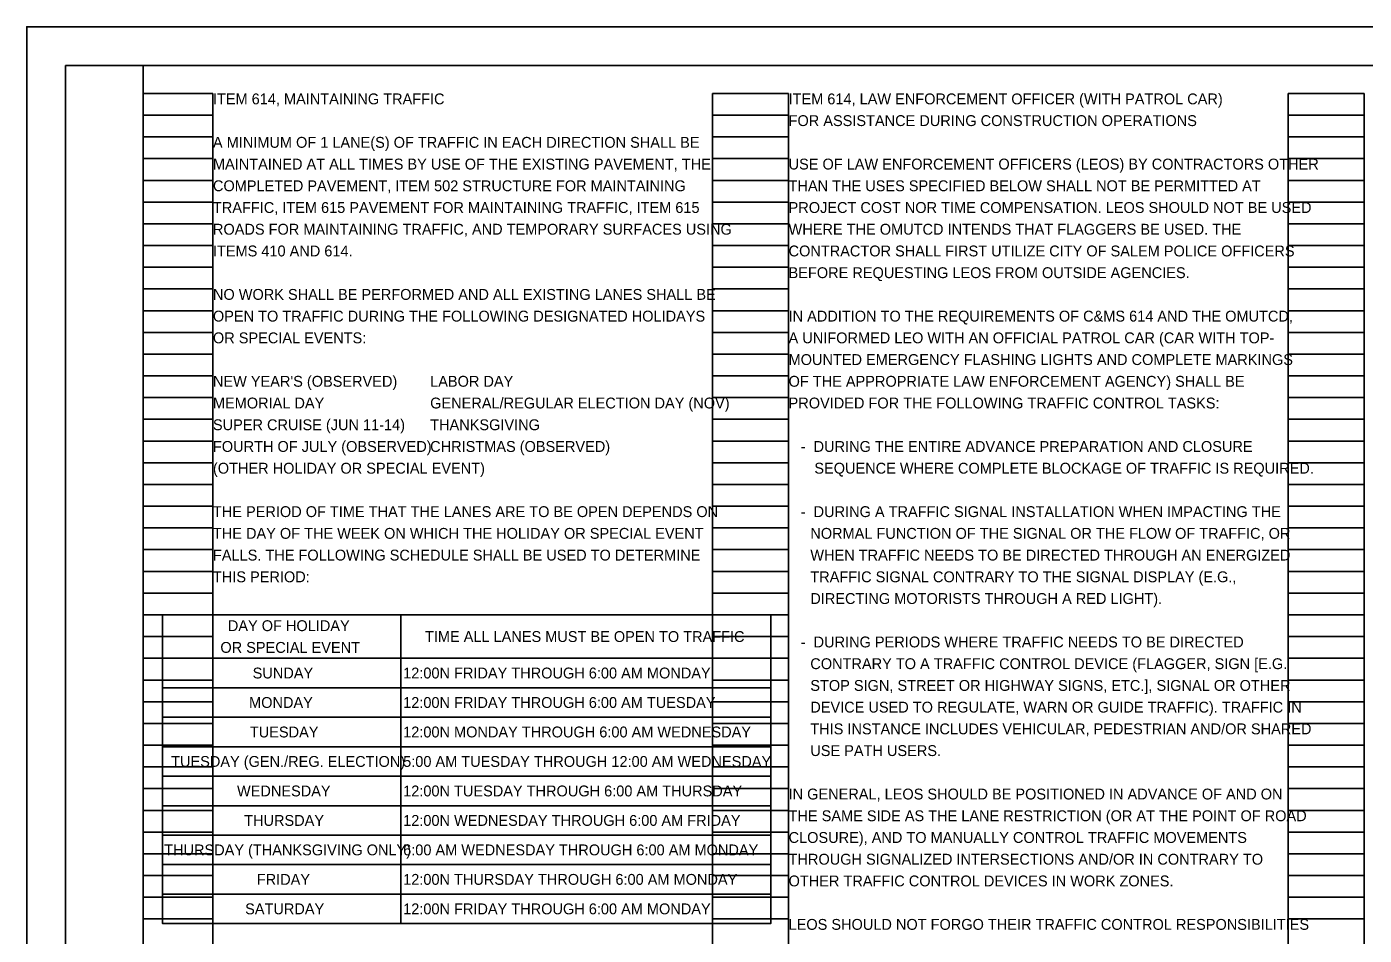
# Model space of a CAD drawing. Extents: x 0 to 34, y 0 to 22.
# Drawn here: x 0 to 17.24, y 10.29 to 22 of the extents above; entities that cross this region are included whole.
import ezdxf

# ---------------------------------------------------------------- set-up
doc = ezdxf.new("R2010")
doc.units = 0
for name, color, linetype in [('SH_Border', 7, 'Continuous'), ('SH_Cut_Line', 7, 'Continuous'), ('SH_Data', 7, 'Continuous'), ('SH_Text', 7, 'Continuous')]:
    doc.layers.add(name, color=color, linetype=linetype)

msp = doc.modelspace()

# ---------------------------------------------------------------- linework, layer by layer
at = {"layer": 'SH_Border'}
for points in [[(0.5, 21.5), (1.5, 21.5), (1.5, 0.5), (0.5, 0.5)], [(1.5, 21.5), (33.5, 21.5), (33.5, 0.5), (1.5, 0.5)]]:
    msp.add_lwpolyline(points, close=True, dxfattribs=at)
at = {"layer": 'SH_Cut_Line'}
msp.add_lwpolyline([(0, 0), (34, 0), (34, 22), (0, 22)], close=True, dxfattribs=at)
at = {"layer": 'SH_Data'}
for p, q in [((1.5, 0.98), (1.5, 21.14)), ((1.5, 21.14), (2.4, 21.14)), ((2.4, 0.98), (2.4, 21.14)), ((8.84, 0.98), (8.84, 21.14)), ((8.84, 21.14), (9.82, 21.14)), ((9.82, 0.98), (9.82, 21.14)), ((16.26, 0.98), (16.26, 21.14)), ((16.26, 21.14), (17.24, 21.14)), ((17.24, 0.98), (17.24, 21.14)), ((1.5, 20.86), (2.4, 20.86)), ((8.84, 20.86), (9.82, 20.86)), ((16.26, 20.86), (17.24, 20.86)), ((1.5, 20.58), (2.4, 20.58)), ((8.84, 20.58), (9.82, 20.58)), ((16.26, 20.58), (17.24, 20.58)), ((1.5, 20.3), (2.4, 20.3)), ((8.84, 20.3), (9.82, 20.3)), ((16.26, 20.3), (17.24, 20.3)), ((1.5, 20.02), (2.4, 20.02)), ((8.84, 20.02), (9.82, 20.02)), ((16.26, 20.02), (17.24, 20.02)), ((1.5, 19.74), (2.4, 19.74)), ((8.84, 19.74), (9.82, 19.74)), ((16.26, 19.74), (17.24, 19.74)), ((1.5, 19.46), (2.4, 19.46)), ((8.84, 19.46), (9.82, 19.46)), ((16.26, 19.46), (17.24, 19.46)), ((1.5, 19.18), (2.4, 19.18)), ((8.84, 19.18), (9.82, 19.18)), ((16.26, 19.18), (17.24, 19.18)), ((1.5, 18.9), (2.4, 18.9)), ((8.84, 18.9), (9.82, 18.9)), ((16.26, 18.9), (17.24, 18.9)), ((1.5, 18.62), (2.4, 18.62)), ((8.84, 18.62), (9.82, 18.62)), ((16.26, 18.62), (17.24, 18.62)), ((1.5, 18.34), (2.4, 18.34)), ((8.84, 18.34), (9.82, 18.34)), ((16.26, 18.34), (17.24, 18.34)), ((1.5, 18.06), (2.4, 18.06)), ((8.84, 18.06), (9.82, 18.06)), ((16.26, 18.06), (17.24, 18.06)), ((1.5, 17.78), (2.4, 17.78)), ((8.84, 17.78), (9.82, 17.78)), ((16.26, 17.78), (17.24, 17.78)), ((1.5, 17.5), (2.4, 17.5)), ((8.84, 17.5), (9.82, 17.5)), ((16.26, 17.5), (17.24, 17.5)), ((1.5, 17.22), (2.4, 17.22)), ((8.84, 17.22), (9.82, 17.22)), ((16.26, 17.22), (17.24, 17.22)), ((1.5, 16.94), (2.4, 16.94)), ((8.84, 16.94), (9.82, 16.94)), ((16.26, 16.94), (17.24, 16.94)), ((1.5, 16.66), (2.4, 16.66)), ((8.84, 16.66), (9.82, 16.66)), ((16.26, 16.66), (17.24, 16.66)), ((1.5, 16.38), (2.4, 16.38)), ((8.84, 16.38), (9.82, 16.38)), ((16.26, 16.38), (17.24, 16.38)), ((1.5, 16.1), (2.4, 16.1)), ((8.84, 16.1), (9.82, 16.1)), ((16.26, 16.1), (17.24, 16.1)), ((1.5, 15.82), (2.4, 15.82)), ((8.84, 15.82), (9.82, 15.82)), ((16.26, 15.82), (17.24, 15.82)), ((1.5, 15.54), (2.4, 15.54)), ((8.84, 15.54), (9.82, 15.54)), ((16.26, 15.54), (17.24, 15.54)), ((1.5, 15.26), (2.4, 15.26)), ((8.84, 15.26), (9.82, 15.26)), ((16.26, 15.26), (17.24, 15.26)), ((1.5, 14.98), (2.4, 14.98)), ((8.84, 14.98), (9.82, 14.98)), ((16.26, 14.98), (17.24, 14.98)), ((1.5, 14.7), (2.4, 14.7)), ((8.84, 14.7), (9.82, 14.7)), ((16.26, 14.7), (17.24, 14.7)), ((1.5, 14.42), (2.4, 14.42)), ((8.84, 14.42), (9.82, 14.42)), ((16.26, 14.42), (17.24, 14.42)), ((1.5, 14.14), (2.4, 14.14)), ((8.84, 14.14), (9.82, 14.14)), ((16.26, 14.14), (17.24, 14.14)), ((1.5, 13.86), (2.4, 13.86)), ((8.84, 13.86), (9.82, 13.86)), ((16.26, 13.86), (17.24, 13.86)), ((1.5, 13.58), (2.4, 13.58)), ((8.84, 13.58), (9.82, 13.58)), ((16.26, 13.58), (17.24, 13.58)), ((1.5, 13.3), (2.4, 13.3)), ((8.84, 13.3), (9.82, 13.3)), ((16.26, 13.3), (17.24, 13.3)), ((1.5, 13.02), (2.4, 13.02)), ((8.84, 13.02), (9.82, 13.02)), ((16.26, 13.02), (17.24, 13.02)), ((1.5, 12.74), (2.4, 12.74)), ((8.84, 12.74), (9.82, 12.74)), ((16.26, 12.74), (17.24, 12.74)), ((1.5, 12.46), (2.4, 12.46)), ((8.84, 12.46), (9.82, 12.46)), ((16.26, 12.46), (17.24, 12.46)), ((1.5, 12.18), (2.4, 12.18)), ((8.84, 12.18), (9.82, 12.18)), ((16.26, 12.18), (17.24, 12.18)), ((1.5, 11.9), (2.4, 11.9)), ((8.84, 11.9), (9.82, 11.9)), ((16.26, 11.9), (17.24, 11.9)), ((1.5, 11.62), (2.4, 11.62)), ((8.84, 11.62), (9.82, 11.62)), ((16.26, 11.62), (17.24, 11.62)), ((1.5, 11.34), (2.4, 11.34)), ((8.84, 11.34), (9.82, 11.34)), ((16.26, 11.34), (17.24, 11.34)), ((1.5, 11.06), (2.4, 11.06)), ((8.84, 11.06), (9.82, 11.06)), ((16.26, 11.06), (17.24, 11.06)), ((1.5, 10.78), (2.4, 10.78)), ((8.84, 10.78), (9.82, 10.78)), ((16.26, 10.78), (17.24, 10.78)), ((1.5, 10.5), (2.4, 10.5)), ((8.84, 10.5), (9.82, 10.5)), ((16.26, 10.5), (17.24, 10.5))]:
    msp.add_line(p, q, dxfattribs=at)
at = {"layer": 'SH_Text'}
for points in [[(1.75, 14.42), (4.82, 14.42), (4.82, 13.86), (1.75, 13.86)], [(4.82, 14.42), (9.59, 14.42), (9.59, 13.86), (4.82, 13.86)], [(1.75, 13.86), (4.82, 13.86), (4.82, 13.48), (1.75, 13.48)], [(4.82, 13.86), (9.59, 13.86), (9.59, 13.48), (4.82, 13.48)], [(1.75, 13.48), (4.82, 13.48), (4.82, 13.1), (1.75, 13.1)], [(4.82, 13.48), (9.59, 13.48), (9.59, 13.1), (4.82, 13.1)], [(1.75, 13.1), (4.82, 13.1), (4.82, 12.72), (1.75, 12.72)], [(4.82, 13.1), (9.59, 13.1), (9.59, 12.72), (4.82, 12.72)], [(1.75, 12.72), (4.82, 12.72), (4.82, 12.34), (1.75, 12.34)], [(4.82, 12.72), (9.59, 12.72), (9.59, 12.34), (4.82, 12.34)], [(1.75, 12.34), (4.82, 12.34), (4.82, 11.96), (1.75, 11.96)], [(4.82, 12.34), (9.59, 12.34), (9.59, 11.96), (4.82, 11.96)], [(1.75, 11.96), (4.82, 11.96), (4.82, 11.58), (1.75, 11.58)], [(4.82, 11.96), (9.59, 11.96), (9.59, 11.58), (4.82, 11.58)], [(1.75, 11.58), (4.82, 11.58), (4.82, 11.2), (1.75, 11.2)], [(4.82, 11.58), (9.59, 11.58), (9.59, 11.2), (4.82, 11.2)], [(1.75, 11.2), (4.82, 11.2), (4.82, 10.82), (1.75, 10.82)], [(4.82, 11.2), (9.59, 11.2), (9.59, 10.82), (4.82, 10.82)], [(1.75, 10.82), (4.82, 10.82), (4.82, 10.44), (1.75, 10.44)], [(4.82, 10.82), (9.59, 10.82), (9.59, 10.44), (4.82, 10.44)]]:
    msp.add_lwpolyline(points, close=True, dxfattribs=at)

# ---------------------------------------------------------------- texts
for s, p in [('ITEM 614, MAINTAINING TRAFFIC', (2.4, 21)), ('ITEM 614, LAW ENFORCEMENT OFFICER (WITH PATROL CAR)', (9.82, 21)), ('FOR ASSISTANCE DURING CONSTRUCTION OPERATIONS', (9.82, 20.72)), ('A MINIMUM OF 1 LANE(S) OF TRAFFIC IN EACH DIRECTION SHALL BE ', (2.4, 20.44)), ('MAINTAINED AT ALL TIMES BY USE OF THE EXISTING PAVEMENT, THE ', (2.4, 20.16)), ('USE OF LAW ENFORCEMENT OFFICERS (LEOS) BY CONTRACTORS OTHER ', (9.82, 20.16)), ('COMPLETED PAVEMENT, ITEM 502 STRUCTURE FOR MAINTAINING ', (2.4, 19.88)), ('THAN THE USES SPECIFIED BELOW SHALL NOT BE PERMITTED AT ', (9.82, 19.88)), ('TRAFFIC, ITEM 615 PAVEMENT FOR MAINTAINING TRAFFIC, ITEM 615 ', (2.4, 19.6)), ('PROJECT COST NOR TIME COMPENSATION. LEOS SHOULD NOT BE USED ', (9.82, 19.6)), ('ROADS FOR MAINTAINING TRAFFIC, AND TEMPORARY SURFACES USING ', (2.4, 19.32)), ('WHERE THE OMUTCD INTENDS THAT FLAGGERS BE USED. THE ', (9.82, 19.32)), ('ITEMS 410 AND 614.', (2.4, 19.04)), ('CONTRACTOR SHALL FIRST UTILIZE CITY OF SALEM POLICE OFFICERS ', (9.82, 19.04)), ('BEFORE REQUESTING LEOS FROM OUTSIDE AGENCIES.', (9.82, 18.76)), ('NO WORK SHALL BE PERFORMED AND ALL EXISTING LANES SHALL BE', (2.4, 18.48)), ('OPEN TO TRAFFIC DURING THE FOLLOWING DESIGNATED HOLIDAYS', (2.4, 18.2)), ('IN ADDITION TO THE REQUIREMENTS OF C&MS 614 AND THE OMUTCD, ', (9.82, 18.2)), ('OR SPECIAL EVENTS:', (2.4, 17.92)), ('A UNIFORMED LEO WITH AN OFFICIAL PATROL CAR (CAR WITH TOP-', (9.82, 17.92)), ('MOUNTED EMERGENCY FLASHING LIGHTS AND COMPLETE MARKINGS ', (9.82, 17.64)), ("NEW YEAR'S (OBSERVED)      ", (2.4, 17.36)), ('LABOR DAY', (5.2, 17.36)), ('OF THE APPROPRIATE LAW ENFORCEMENT AGENCY) SHALL BE ', (9.82, 17.36)), ('MEMORIAL DAY ', (2.4, 17.08)), ('GENERAL/REGULAR ELECTION DAY (NOV)', (5.2, 17.08)), ('PROVIDED FOR THE FOLLOWING TRAFFIC CONTROL TASKS:', (9.82, 17.08)), ('SUPER CRUISE (JUN 11-14)', (2.4, 16.8)), ('THANKSGIVING    ', (5.2, 16.8)), ('FOURTH OF JULY (OBSERVED)', (2.4, 16.52)), ('CHRISTMAS (OBSERVED)', (5.2, 16.52)), ('   -  DURING THE ENTIRE ADVANCE PREPARATION AND CLOSURE ', (9.82, 16.52)), ('(OTHER HOLIDAY OR SPECIAL EVENT)', (2.4, 16.24)), (' SEQUENCE WHERE COMPLETE BLOCKAGE OF TRAFFIC IS REQUIRED.', (10.1, 16.24)), ('THE PERIOD OF TIME THAT THE LANES ARE TO BE OPEN DEPENDS ON', (2.4, 15.68)), ('   -  DURING A TRAFFIC SIGNAL INSTALLATION WHEN IMPACTING THE ', (9.82, 15.68)), ('THE DAY OF THE WEEK ON WHICH THE HOLIDAY OR SPECIAL EVENT ', (2.4, 15.4)), ('NORMAL FUNCTION OF THE SIGNAL OR THE FLOW OF TRAFFIC, OR ', (10.1, 15.4)), ('FALLS. THE FOLLOWING SCHEDULE SHALL BE USED TO DETERMINE', (2.4, 15.12)), ('WHEN TRAFFIC NEEDS TO BE DIRECTED THROUGH AN ENERGIZED ', (10.1, 15.12)), ('THIS PERIOD:', (2.4, 14.84)), ('TRAFFIC SIGNAL CONTRARY TO THE SIGNAL DISPLAY (E.G., ', (10.1, 14.84)), ('DIRECTING MOTORISTS THROUGH A RED LIGHT).', (10.1, 14.56)), ('DAY OF HOLIDAY', (2.592, 14.21)), ('TIME ALL LANES MUST BE OPEN TO TRAFFIC', (5.133, 14.07)), ('   -  DURING PERIODS WHERE TRAFFIC NEEDS TO BE DIRECTED ', (9.82, 14)), ('OR SPECIAL EVENT', (2.496, 13.93)), ('CONTRARY TO A TRAFFIC CONTROL DEVICE (FLAGGER, SIGN [E.G. ', (10.1, 13.72)), ('SUNDAY', (2.912, 13.6)), ('12:00N FRIDAY THROUGH 6:00 AM MONDAY', (4.852, 13.6)), ('STOP SIGN, STREET OR HIGHWAY SIGNS, ETC.], SIGNAL OR OTHER ', (10.1, 13.44)), ('MONDAY', (2.866, 13.22)), ('12:00N FRIDAY THROUGH 6:00 AM TUESDAY', (4.852, 13.22)), ('DEVICE USED TO REGULATE, WARN OR GUIDE TRAFFIC). TRAFFIC IN ', (10.1, 13.16)), ('TUESDAY', (2.876, 12.84)), ('12:00N MONDAY THROUGH 6:00 AM WEDNESDAY', (4.852, 12.84)), ('THIS INSTANCE INCLUDES VEHICULAR, PEDESTRIAN AND/OR SHARED ', (10.1, 12.88)), ('TUESDAY (GEN./REG. ELECTION)', (1.861, 12.46)), ('5:00 AM TUESDAY THROUGH 12:00 AM WEDNESDAY', (4.852, 12.46)), ('USE PATH USERS.', (10.1, 12.6)), ('WEDNESDAY', (2.71, 12.08)), ('12:00N TUESDAY THROUGH 6:00 AM THURSDAY', (4.852, 12.08)), ('IN GENERAL, LEOS SHOULD BE POSITIONED IN ADVANCE OF AND ON ', (9.82, 12.04)), ('THE SAME SIDE AS THE LANE RESTRICTION (OR AT THE POINT OF ROAD ', (9.82, 11.76)), ('THURSDAY', (2.802, 11.7)), ('12:00N WEDNESDAY THROUGH 6:00 AM FRIDAY', (4.852, 11.7)), ('CLOSURE), AND TO MANUALLY CONTROL TRAFFIC MOVEMENTS ', (9.82, 11.48)), ('THURSDAY (THANKSGIVING ONLY)', (1.771, 11.32)), ('6:00 AM WEDNESDAY THROUGH 6:00 AM MONDAY', (4.852, 11.32)), ('THROUGH SIGNALIZED INTERSECTIONS AND/OR IN CONTRARY TO ', (9.82, 11.2)), ('FRIDAY', (2.965, 10.94)), ('12:00N THURSDAY THROUGH 6:00 AM MONDAY', (4.852, 10.94)), ('OTHER TRAFFIC CONTROL DEVICES IN WORK ZONES.', (9.82, 10.92)), ('SATURDAY', (2.815, 10.56)), ('12:00N FRIDAY THROUGH 6:00 AM MONDAY', (4.852, 10.56)), ('LEOS SHOULD NOT FORGO THEIR TRAFFIC CONTROL RESPONSIBILITIES ', (9.82, 10.36))]:
    msp.add_text(s, height=0.14, dxfattribs=at).set_placement(p)

doc.saveas('drawing.dxf')
